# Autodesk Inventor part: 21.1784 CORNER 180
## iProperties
Created: 2007-04
Part Number: 21.1784 CORNER 180
Document SubType Name: Modeling
Designer: Andy Moles
Material: Aluminum-6061
Density: 2.71 g/cm^3
Author: Andy Moles
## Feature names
1. Extrusion6
2. Extrusion7
3. Extrusion8
4. Extrusion9
5. Extrusion10
6. Mirror1
7. Mirror2
8. Extrusion11
9. Mirror3
